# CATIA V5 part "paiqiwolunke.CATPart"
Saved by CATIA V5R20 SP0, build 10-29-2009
Part number: paiqiwolunke
Material "无"
Bounding box of the stored display mesh (mm): x -181.093 to 108.493, y -161.62 to 108.435, z -157.748 to -20.517
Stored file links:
  C:\Users\Administrator\Desktop\paiqiwolunke.CATPart
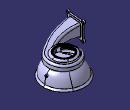
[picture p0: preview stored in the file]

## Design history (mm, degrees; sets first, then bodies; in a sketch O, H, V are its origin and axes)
Body1 (main body), material "无"
  DatumSurface1
  Sketch1 on face of DatumSurface1, origin (0, 0, -46.0268), H (1, 0, 0), V (0, 1, 0)
    circle A1 centre (0, 0) radius 48
    circle A2 centre (0, 0) radius 41
    radius A1 = 48
    radius A2 = 41
  Pad1: profile Sketch1, direction (0, 0, -1), length 4
  Fillet1: radius 1, on edge [face of Pad1 from Sketch1.A1 | start face of Pad1]
  Plane1: type Offset, RefPlane xy-plane, Offset -72
  Sketch2 on Plane1, origin (0, 0, -72), H (1, 0, 0), V (0, 1, 0)
    arc A1 centre (0, 0) radius 62.4525 from (38.718, -49.0024) to (-57.1138, -25.2652) ccw
    spline S1 through (38.718, -49.0024) (-43.2646, -95.0784) (-167.0197, -110.3887)
    point P2 (38.718, -49.0024)
    spline S2 through (-57.1138, -25.2652) (-47.5761, -37.3017) (-28.4968, -46.2262)
    point P3 (38.718, -49.0024)
    point P4 (-57.1138, -25.2652)
    coincidence: P3 A1, P3 P2, P4 A1
    tangency: S1 A1
  Set1
    Point1: type OnCurve, Support Sketch2, Length 107.0833 {= length(Sketch2) / 5}
    Point2: type OnCurve, Support Sketch2, Length 214.1665 {= (length(Sketch2)) * 2 / 5}
    Point3: type OnCurve, Support Sketch2, Length 321.2498 {= (length(Sketch2)) * 3 / 5}
    Point4: type OnCurve, Support Sketch2, Length 428.3331 {= (length(Sketch2)) * 4 / 5}
  Plane2: type Normal, Curve Sketch2, RefPoint vertex of Sketch2
  Plane3: type Normal, Curve Sketch2, RefPoint Point1
  Plane4: type Normal, Curve Sketch2, RefPoint Point2
  Plane5: type Normal, Curve Sketch2, RefPoint Point3
  Plane6: type Normal, Curve Sketch2, RefPoint Point4
  Plane7: type Normal, Curve Sketch2, RefPoint vertex of Sketch2
  Sketch3 on Plane2, origin (-156.975, 12.7997, 0), H (0.0813, 0.9967, 0), V (0, 0, 1)
    point P1 (-157.5972, -38)
    line L1 (-149.3665, -38) -> (-97.6756, -38)
    line L2 (-89.5972, -46.0784) -> (-89.5972, -98.0619)
    line L3 (-97.5353, -106) -> (-148.2395, -106)
    line L4 (-157.5972, -96.6423) -> (-157.5972, -46.2307)
    point P2 (-89.5972, -106)
    point P3 (-157.5972, -106)
    reference projected point E1 (-123.5972, -72) from vertex of Sketch2
    reference projected point E2 (-123.5972, -72) from vertex of Sketch2
    arc A1 centre (-149.3665, -46.2307) radius 8.2307 from (-157.5972, -46.2307) to (-149.3665, -38) cw
    arc A2 centre (-97.6756, -46.0784) radius 8.0784 from (-97.6756, -38) to (-89.5972, -46.0784) cw
    arc A3 centre (-97.5353, -98.0619) radius 7.9381 from (-89.5972, -98.0619) to (-97.5353, -106) cw
    arc A4 centre (-148.2395, -96.6423) radius 9.3577 from (-148.2395, -106) to (-157.5972, -96.6423) cw
    arc A5 centre (-97.5353, -98.0619) radius 5.5029 from (-97.5353, -103.5648) to (-92.0324, -98.0619) ccw
    line L5 (-92.0324, -98.0619) -> (-92.0324, -46.0784)
    arc A6 centre (-97.6756, -46.0784) radius 5.6432 from (-92.0324, -46.0784) to (-97.6756, -40.4352) ccw
    line L6 (-149.3665, -40.4352) -> (-97.6756, -40.4352)
    arc A7 centre (-149.3665, -46.2307) radius 5.7955 from (-149.3665, -40.4352) to (-155.162, -46.2307) ccw
    line L7 (-155.162, -46.2307) -> (-155.162, -96.6423)
    arc A8 centre (-148.2395, -96.6423) radius 6.9225 from (-155.162, -96.6423) to (-148.2395, -103.5648) ccw
    line L8 (-97.5353, -103.5648) -> (-148.2395, -103.5648)
    distance P3 P1 = 68
    radius A1 = 8.2307
    radius A2 = 8.0784
    distance P2 P3 = 68
    radius A3 = 7.9381
    radius A4 = 9.3577
    horizontal: L1 H, L3 H
    vertical: L2 V, L4 V
    equidistance: L4 L2 E1, L3 L1 E2
    coincidence: L4 P1, L1 P1, L2 P2, L3 P2, L3 P3, L4 P3
    tangency: A1 L4, A1 L1, A2 L1, A2 L2, A3 L2, A3 L3, A4 L3, A4 L4
  Sketch4 on Plane3, origin (-83.5491, -21.2744, 0), H (-0.2735, 0.9619, 0), V (0, 0, 1)
    point P1 (-106.6399, -48)
    line L1 (-97.0585, -48) -> (-68.4469, -48)
    line L2 (-58.6399, -57.8069) -> (-58.6399, -87.414)
    line L3 (-67.2259, -96) -> (-98.3631, -96)
    line L4 (-106.6399, -87.7232) -> (-106.6399, -57.5814)
    point P2 (-58.6399, -96)
    point P3 (-106.6399, -96)
    reference projected point E1 (-82.6399, -72) from Point1
    reference projected point E2 (-82.6399, -72) from Point1
    arc A1 centre (-98.3631, -87.7232) radius 8.2768 from (-106.6399, -87.7232) to (-98.3631, -96) ccw
    arc A2 centre (-67.2259, -87.414) radius 8.586 from (-67.2259, -96) to (-58.6399, -87.414) ccw
    arc A3 centre (-68.4469, -57.8069) radius 9.8069 from (-58.6399, -57.8069) to (-68.4469, -48) ccw
    arc A4 centre (-97.0585, -57.5814) radius 9.5814 from (-97.0585, -48) to (-106.6399, -57.5814) ccw
    arc A5 centre (-97.2584, -57.5576) radius 7.6536 from (-97.2584, -49.904) to (-104.912, -57.5576) ccw
    line L5 (-104.912, -57.5576) -> (-104.912, -87.6994)
    arc A6 centre (-98.563, -87.6994) radius 6.349 from (-104.912, -87.6994) to (-98.563, -94.0484) ccw
    line L6 (-67.4258, -94.0484) -> (-98.563, -94.0484)
    arc A7 centre (-67.4258, -87.3902) radius 6.6582 from (-67.4258, -94.0484) to (-60.7676, -87.3902) ccw
    line L7 (-60.7676, -87.3902) -> (-60.7676, -57.7831)
    arc A8 centre (-68.6467, -57.7831) radius 7.8792 from (-60.7676, -57.7831) to (-68.6467, -49.904) ccw
    line L8 (-97.2584, -49.904) -> (-68.6467, -49.904)
    distance P3 P1 = 48
    distance P2 P3 = 48
    radius A1 = 8.2768
    radius A2 = 8.586
    radius A3 = 9.8069
    radius A4 = 9.5814
    horizontal: L1 H, L3 H
    vertical: L2 V, L4 V
    equidistance: L3 L1 E1, L4 L2 E2
    coincidence: L4 P3, L3 P3, L3 P2, L2 P2, L1 P1, L4 P1
    tangency: A1 L4, A1 L3, A2 L3, A2 L2, A3 L2, A3 L1, A4 L1, A4 L4
  Sketch5 on Plane4, origin (-4.1333, -2.5181, 0), H (-0.6055, 0.7958, 0), V (0, 0, 1)
    point P1 (-82.9955, -52)
    line L1 (-73.3955, -52) -> (-52.5955, -52)
    line L2 (-42.9955, -61.6) -> (-42.9955, -82.4)
    line L3 (-52.5955, -92) -> (-73.3955, -92)
    line L4 (-82.9955, -82.4) -> (-82.9955, -61.6)
    point P2 (-42.9955, -92)
    point P3 (-82.9955, -92)
    reference projected point E1 (-62.9955, -72) from Point2
    reference projected point E2 (-62.9955, -72) from Point2
    arc A1 centre (-73.3955, -82.4) radius 9.6 from (-82.9955, -82.4) to (-73.3955, -92) ccw
    arc A2 centre (-52.5955, -82.4) radius 9.6 from (-52.5955, -92) to (-42.9955, -82.4) ccw
    arc A3 centre (-52.5955, -61.6) radius 9.6 from (-52.5955, -52) to (-42.9955, -61.6) cw
    arc A4 centre (-73.3955, -61.6) radius 9.6 from (-73.3955, -52) to (-82.9955, -61.6) ccw
    arc A5 centre (-49.6836, -82.554) radius 7.5157 from (-49.6836, -90.0697) to (-42.1679, -82.554) ccw
    line L5 (-42.1679, -82.554) -> (-42.1679, -61.754)
    arc A6 centre (-49.6836, -61.754) radius 7.5157 from (-42.1679, -61.754) to (-49.6836, -54.2383) ccw
    line L6 (-70.4836, -54.2383) -> (-49.6836, -54.2383)
    arc A7 centre (-70.4836, -61.754) radius 7.5157 from (-70.4836, -54.2383) to (-77.9992, -61.754) ccw
    line L7 (-77.9992, -61.754) -> (-77.9992, -82.554)
    arc A8 centre (-70.4836, -82.554) radius 7.5157 from (-77.9992, -82.554) to (-70.4836, -90.0697) ccw
    line L8 (-49.6836, -90.0697) -> (-70.4836, -90.0697)
    distance P3 P1 = 40
    distance P2 P3 = 40
    radius A1 = 9.6
    radius A2 = 9.6
    radius A3 = 9.6
    radius A4 = 9.6
    horizontal: L1 H, L3 H
    vertical: L2 V, L4 V
    equidistance: L4 L2 E1, L3 L1 E2
    coincidence: L4 P3, L3 P3, L3 P2, L2 P2, L1 P1, L4 P1
    tangency: A1 L4, A1 L3, A2 L3, A2 L2, A3 L1, A3 L2, A4 L1, A4 L4
  Sketch6 on Plane5, origin (0, 0, 0), H (-0.7537, -0.6572, 0), V (0, 0, 1)
    point P1 (-80.4525, -54)
    line L1 (-70.8525, -54) -> (-54.0525, -54)
    line L2 (-44.4525, -63.6) -> (-44.4525, -80.4)
    line L3 (-54.0525, -90) -> (-70.8525, -90)
    line L4 (-80.4525, -80.4) -> (-80.4525, -63.6)
    point P2 (-44.4525, -90)
    point P3 (-80.4525, -90)
    reference projected point E1 (-62.4525, -72) from Point3
    reference projected point E2 (-62.4525, -72) from Point3
    arc A1 centre (-70.8525, -63.6) radius 9.6 from (-70.8525, -54) to (-80.4525, -63.6) ccw
    arc A2 centre (-70.8525, -80.4) radius 9.6 from (-80.4525, -80.4) to (-70.8525, -90) ccw
    arc A3 centre (-54.0525, -80.4) radius 9.6 from (-54.0525, -90) to (-44.4525, -80.4) ccw
    arc A4 centre (-54.0525, -63.6) radius 9.6 from (-44.4525, -63.6) to (-54.0525, -54) ccw
    arc A5 centre (-50.5792, -80.4111) radius 7.8791 from (-50.5792, -88.2902) to (-42.7001, -80.4111) ccw
    line L5 (-42.7001, -80.4111) -> (-42.7001, -63.6111)
    arc A6 centre (-50.5792, -63.6111) radius 7.8791 from (-42.7001, -63.6111) to (-50.5792, -55.732) ccw
    line L6 (-67.3792, -55.732) -> (-50.5792, -55.732)
    arc A7 centre (-67.3792, -63.6111) radius 7.8791 from (-67.3792, -55.732) to (-75.2584, -63.6111) ccw
    line L7 (-75.2584, -63.6111) -> (-75.2584, -80.4111)
    arc A8 centre (-67.3792, -80.4111) radius 7.8791 from (-75.2584, -80.4111) to (-67.3792, -88.2902) ccw
    line L8 (-50.5792, -88.2902) -> (-67.3792, -88.2902)
    distance P3 P1 = 36
    radius A1 = 9.6
    distance P2 P3 = 36
    radius A2 = 9.6
    radius A3 = 9.6
    radius A4 = 9.6
    horizontal: L1 H, L3 H
    vertical: L2 V, L4 V
    equidistance: L2 L4 E1, L1 L3 E2
    coincidence: L1 P1, L4 P1, L4 P3, L3 P3, L3 P2, L2 P2
    tangency: A1 L1, A1 L4, A2 L4, A2 L3, A3 L3, A3 L2, A4 L2, A4 L1
  Sketch7 on Plane6, origin (0, 0, 0), H (0.7585, -0.6517, 0), V (0, 0, 1)
    line L1 (-65.699, -54.5) -> (-49.699, -54.5)
    line L2 (-40.199, -64) -> (-40.199, -80)
    line L3 (-49.699, -89.5) -> (-65.699, -89.5)
    line L4 (-75.199, -80) -> (-75.199, -64)
    reference projected point E1 (-62.4525, -72) from Point4
    arc A1 centre (-65.699, -80) radius 9.5 from (-75.199, -80) to (-65.699, -89.5) ccw
    arc A2 centre (-49.699, -80) radius 9.5 from (-40.199, -80) to (-49.699, -89.5) cw
    arc A3 centre (-49.699, -64) radius 9.5 from (-49.699, -54.5) to (-40.199, -64) cw
    arc A4 centre (-65.699, -64) radius 9.5 from (-65.699, -54.5) to (-75.199, -64) ccw
    line L5 (-46.6872, -88.3521) -> (-62.6872, -88.3521)
    arc A5 centre (-62.6872, -80.0426) radius 8.3095 from (-70.9967, -80.0426) to (-62.6872, -88.3521) ccw
    line L6 (-70.9967, -64.0426) -> (-70.9967, -80.0426)
    arc A6 centre (-62.6872, -64.0426) radius 8.3095 from (-62.6872, -55.7331) to (-70.9967, -64.0426) ccw
    line L7 (-62.6872, -55.7331) -> (-46.6872, -55.7331)
    arc A7 centre (-46.6872, -64.0426) radius 8.3095 from (-38.3777, -64.0426) to (-46.6872, -55.7331) ccw
    line L8 (-38.3777, -80.0426) -> (-38.3777, -64.0426)
    arc A8 centre (-46.6872, -80.0426) radius 8.3095 from (-46.6872, -88.3521) to (-38.3777, -80.0426) ccw
    distance L4 L2 = 35
    distance L3 L1 = 35
    radius A1 = 9.5
    radius A2 = 9.5
    radius A3 = 9.5
    radius A4 = 9.5
    horizontal: L1 H, L3 H
    vertical: L2 V, L4 V
    equidistance: L1 L3 E1
    tangency: A1 L4, A1 L3, A2 L2, A2 L3, A3 L1, A3 L2, A4 L1, A4 L4
  Sketch8 on Plane7, origin (-18.4459, 3.7125, 0), H (0.1973, 0.9803, 0), V (0, 0, 1)
    point P1 (-53.4662, -59)
    line L1 (-42.6821, -59) -> (-38.0662, -59)
    line L2 (-33.4662, -63.6) -> (-33.4662, -80.4)
    line L3 (-38.0662, -85) -> (-42.2918, -85)
    line L4 (-53.4662, -73.8257) -> (-53.4662, -69.7841)
    point P2 (-33.4662, -85)
    point P3 (-53.4662, -85)
    reference projected point E1 (-50.9401, -72) from vertex of Sketch2
    arc A1 centre (-42.6821, -69.7841) radius 10.7841 from (-42.6821, -59) to (-53.4662, -69.7841) ccw
    arc A2 centre (-42.2918, -73.8257) radius 11.1743 from (-53.4662, -73.8257) to (-42.2918, -85) ccw
    arc A3 centre (-38.0662, -80.4) radius 4.6 from (-38.0662, -85) to (-33.4662, -80.4) ccw
    arc A4 centre (-38.0662, -63.6) radius 4.6 from (-38.0662, -59) to (-33.4662, -63.6) cw
    line L5 (-31.7117, -80.7328) -> (-31.7117, -63.9328)
    arc A5 centre (-35.0688, -63.9328) radius 3.3571 from (-31.7117, -63.9328) to (-35.0688, -60.5757) ccw
    line L6 (-39.6847, -60.5757) -> (-35.0688, -60.5757)
    arc A6 centre (-39.6847, -70.1169) radius 9.5412 from (-39.6847, -60.5757) to (-49.2259, -70.1169) ccw
    line L7 (-49.2259, -70.1169) -> (-49.2259, -74.1584)
    arc A7 centre (-39.2945, -74.1584) radius 9.9315 from (-49.2259, -74.1584) to (-39.2945, -84.0899) ccw
    line L8 (-35.0688, -84.0899) -> (-39.2945, -84.0899)
    arc A8 centre (-35.0688, -80.7328) radius 3.3571 from (-35.0688, -84.0899) to (-31.7117, -80.7328) ccw
    distance P3 P1 = 26
    radius A1 = 10.7841
    distance P2 P3 = 20
    radius A2 = 11.1743
    radius A3 = 4.6
    radius A4 = 4.6
    horizontal: L1 H, L3 H
    vertical: L2 V, L4 V
    equidistance: L3 L1 E1
    coincidence: L1 P1, L4 P1, L4 P3, L3 P3, L3 P2, L2 P2
    tangency: A1 L1, A1 L4, A2 L4, A2 L3, A3 L3, A3 L2, A4 L1, A4 L2
  MultiExtract1: ListOfMultiExtractConstraints (MultiExtractConstraint Sketch3.L4; MultiExtractConstraint Sketch3.A4; MultiExtractConstraint Sketch3.L3; MultiExtractConstraint Sketch3.A3; MultiExtractConstraint Sketch3.L2; MultiExtractConstraint Sketch3.A2; MultiExtractConstraint Sketch3.L1; MultiExtractConstraint Sketch3.A1)
  MultiExtract2: ListOfMultiExtractConstraints (MultiExtractConstraint Sketch4.A1; MultiExtractConstraint Sketch4.L3; MultiExtractConstraint Sketch4.A2; MultiExtractConstraint Sketch4.L2; MultiExtractConstraint Sketch4.A3; MultiExtractConstraint Sketch4.L1; MultiExtractConstraint Sketch4.A4; MultiExtractConstraint Sketch4.L4)
  MultiExtract3: ListOfMultiExtractConstraints (MultiExtractConstraint Sketch5.L4; MultiExtractConstraint Sketch5.A1; MultiExtractConstraint Sketch5.L3; MultiExtractConstraint Sketch5.A2; MultiExtractConstraint Sketch5.L2; MultiExtractConstraint Sketch5.A3; MultiExtractConstraint Sketch5.L1; MultiExtractConstraint Sketch5.A4)
  MultiExtract4: ListOfMultiExtractConstraints (MultiExtractConstraint Sketch6.A3; MultiExtractConstraint Sketch6.L3; MultiExtractConstraint Sketch6.A2; MultiExtractConstraint Sketch6.L4; MultiExtractConstraint Sketch6.A1; MultiExtractConstraint Sketch6.L1; MultiExtractConstraint Sketch6.A4; MultiExtractConstraint Sketch6.L2)
  MultiExtract5: ListOfMultiExtractConstraints (MultiExtractConstraint Sketch7.L4; MultiExtractConstraint Sketch7.A1; MultiExtractConstraint Sketch7.L3; MultiExtractConstraint Sketch7.A2; MultiExtractConstraint Sketch7.L2; MultiExtractConstraint Sketch7.A3; MultiExtractConstraint Sketch7.L1; MultiExtractConstraint Sketch7.A4)
  MultiExtract6: ListOfMultiExtractConstraints (MultiExtractConstraint Sketch8.A1; MultiExtractConstraint Sketch8.L1; MultiExtractConstraint Sketch8.A4; MultiExtractConstraint Sketch8.L2; MultiExtractConstraint Sketch8.A3; MultiExtractConstraint Sketch8.L3; MultiExtractConstraint Sketch8.A2; MultiExtractConstraint Sketch8.L4)
  Loft1: solid, Sections (MultiExtract1; MultiExtract2; MultiExtract3; MultiExtract4; MultiExtract5; MultiExtract6)
  MultiExtract7: ListOfMultiExtractConstraints (MultiExtractConstraint Sketch3.L6; MultiExtractConstraint Sketch3.A6; MultiExtractConstraint Sketch3.L5; MultiExtractConstraint Sketch3.A5; MultiExtractConstraint Sketch3.L8; MultiExtractConstraint Sketch3.A8; MultiExtractConstraint Sketch3.L7; MultiExtractConstraint Sketch3.A7)
  MultiExtract8: ListOfMultiExtractConstraints (MultiExtractConstraint Sketch4.A5; MultiExtractConstraint Sketch4.L5; MultiExtractConstraint Sketch4.A6; MultiExtractConstraint Sketch4.L6; MultiExtractConstraint Sketch4.A7; MultiExtractConstraint Sketch4.L7; MultiExtractConstraint Sketch4.A8; MultiExtractConstraint Sketch4.L8)
  MultiExtract9: ListOfMultiExtractConstraints (MultiExtractConstraint Sketch5.L7; MultiExtractConstraint Sketch5.A8; MultiExtractConstraint Sketch5.L8; MultiExtractConstraint Sketch5.A7; MultiExtractConstraint Sketch5.L6; MultiExtractConstraint Sketch5.A6; MultiExtractConstraint Sketch5.L5; MultiExtractConstraint Sketch5.A5)
  MultiExtract10: ListOfMultiExtractConstraints (MultiExtractConstraint Sketch6.L8; MultiExtractConstraint Sketch6.A8; MultiExtractConstraint Sketch6.L7; MultiExtractConstraint Sketch6.A7; MultiExtractConstraint Sketch6.L6; MultiExtractConstraint Sketch6.A6; MultiExtractConstraint Sketch6.L5; MultiExtractConstraint Sketch6.A5)
  MultiExtract11: ListOfMultiExtractConstraints (MultiExtractConstraint Sketch7.L7; MultiExtractConstraint Sketch7.A6; MultiExtractConstraint Sketch7.L6; MultiExtractConstraint Sketch7.A5; MultiExtractConstraint Sketch7.L5; MultiExtractConstraint Sketch7.A8; MultiExtractConstraint Sketch7.L8; MultiExtractConstraint Sketch7.A7)
  MultiExtract12: ListOfMultiExtractConstraints (MultiExtractConstraint Sketch8.L5; MultiExtractConstraint Sketch8.A8; MultiExtractConstraint Sketch8.A7; MultiExtractConstraint Sketch8.L8; MultiExtractConstraint Sketch8.A6; MultiExtractConstraint Sketch8.L6; MultiExtractConstraint Sketch8.A5; MultiExtractConstraint Sketch8.L7)
  Loft2: solid, Sections (MultiExtract7; MultiExtract8; MultiExtract9; MultiExtract10; MultiExtract11; MultiExtract12)
  Plane8: type Offset, RefPlane Plane1, Offset -15
  Plane9: type Offset, RefPlane Plane1, Offset 12
  Sketch9 on Plane9, origin (0, 0, -60), H (1, 0, 0), V (0, 1, 0)
    circle A1 centre (1.3796, -4.5256) radius 61.7151
  Loft3: Sections (edge [face of Pad1 from Sketch1.A2 | end face of Pad1]; Sketch9)
  ThickSurface1: Surface Loft3, TopOffset 5, BotOffset 0
  Sketch10 on Plane8, origin (0, 0, -87), H (1, 0, 0), V (0, 1, 0)
    circle A1 centre (2.4934, -2.0884) radius 61.7432
  Plane10: type Offset, RefPlane Plane8, Offset -32
  Plane11: type Offset, RefPlane Plane10, Offset -28
  Sketch11 on Plane10, origin (0, 0, -119), H (1, 0, 0), V (0, 1, 0)
    circle A1 centre (2.4934, -2.0884) radius 89.8824
    reference projected circle E1 centre (2.4934, -2.0884) radius 61.7432 from Sketch10.A1
    concentricity: A1 E1
  Sketch12 on Plane11, origin (0, 0, -147), H (1, 0, 0), V (0, 1, 0)
    circle A1 centre (0, 0) radius 98.0083
  Loft4: Sections (Sketch10; Sketch11; Sketch12)
  ThickSurface2: Surface Loft4, TopOffset 2, BotOffset 3
  Plane12: type Offset, RefPlane Plane8, Offset -12
  Sketch13 on Plane12, origin (0, 0, -99), H (1, 0, 0), V (0, 1, 0)
    circle A1 centre (0, 0) radius 20.54
    circle A2 centre (-0.0225, 0.0191) radius 68.5173
    reference projected curve E1 from edge [face of ThickSurface2 | face of ThickSurface2]
    concentricity: A2 E1
  Pad2: profile Sketch13, direction (0, 0, 1), length 3
  Fillet2: radius 1, on edge [face of Pad2 from Sketch13.A1 | start face of Pad2]; edge [end face of Pad2 | face of Pad2 from Sketch13.A1]
  Sketch14 on Plane1, origin (0, 0, -72), H (1, 0, 0), V (0, 1, 0)
    arc A1 centre (0, 0) radius 69.3759 from (-69.0256, 6.9637) to (-19.0511, -66.7089) ccw
  Plane13: type Normal, Curve Sketch14
  Sketch15 on Plane13, origin (0, 0, 0), H (0.8276, 0.5614, 0), V (0, 0, 1)
    spline S1 through (-59.6577, -53.5603) (-70.3652, -71.7344) (-59.2766, -87.9066)
  Sweep1: type Unspec, Profile Sketch15, Guide Sketch14, AngleRef 0
  ThickSurface3: Surface Sweep1, TopOffset 2, BotOffset 1
  Sketch16 on face of Loft1, origin (-156.975, 12.7997, 0), H (0.0813, 0.9967, 0), V (0, 0, 1)
    projected line E1 (-92.0324, -98.0619) -> (-92.0324, -46.0784) from edge [face of Loft2 | face of Loft1]
    projected arc E2 centre (-97.6756, -46.0784) radius 5.6432 from (-92.0324, -46.0784) to (-97.6756, -40.4352) ccw from edge [face of Loft2 | face of Loft1]
    projected line E3 (-97.6756, -40.4352) -> (-149.3665, -40.4352) from edge [face of Loft2 | face of Loft1]
    projected arc E4 centre (-149.3666, -46.2307) radius 5.7955 from (-149.3665, -40.4352) to (-155.162, -46.2307) ccw from edge [face of Loft2 | face of Loft1]
    projected line E5 (-155.162, -46.2307) -> (-155.162, -96.6423) from edge [face of Loft2 | face of Loft1]
    projected arc E6 centre (-148.2396, -96.6424) radius 6.9225 from (-155.162, -96.6423) to (-148.2395, -103.5648) ccw from edge [face of Loft2 | face of Loft1]
    projected line E7 (-148.2395, -103.5648) -> (-97.5353, -103.5648) from edge [face of Loft2 | face of Loft1]
    projected arc E8 centre (-97.5353, -98.0619) radius 5.5029 from (-97.5353, -103.5648) to (-92.0324, -98.0619) ccw from edge [face of Loft2 | face of Loft1]
    point P17 (-81.1295, -101.0273)
    point P18 (-81.1295, -103.5648)
    line L1 (-80.0324, -36.4352) -> (-80.0324, -107.5648)
    line L2 (-88.0324, -115.5648) -> (-159.162, -115.5648)
    circle A1 centre (-167.162, -28.4352) radius 5
    circle A2 centre (-80.0324, -28.4352) radius 5
    circle A3 centre (-80.0324, -115.5648) radius 5
    arc A4 centre (-167.162, -28.4352) radius 8 from (-159.162, -28.4352) to (-167.162, -36.4352) ccw
    arc A5 centre (-80.0324, -28.4352) radius 8 from (-80.0324, -36.4352) to (-88.0324, -28.4352) ccw
    arc A6 centre (-167.162, -115.5648) radius 8 from (-167.162, -107.5648) to (-159.162, -115.5648) ccw
    arc A7 centre (-80.0324, -115.5648) radius 8 from (-88.0324, -115.5648) to (-80.0324, -107.5648) ccw
    line L3 (-159.162, -28.4352) -> (-88.0324, -28.4352)
    line L4 (-167.162, -107.5648) -> (-167.162, -36.4352)
    circle A8 centre (-167.162, -115.5648) radius 5
    point P31 (-167.162, -112.2727)
    distance L1 E1 = 12
    distance E7 L2 = 12
    radius A3 = 5
    radius A1 = 5
    radius A2 = 5
    radius A4 = 8
    radius A6 = 8
    radius A7 = 8
    radius A5 = 8
    radius A8 = 5
    horizontal: L2 H, L3 H
    vertical: L1 V, L4 V
  Pad3: profile Sketch16, direction (-0.9967, 0.0813, 0), length 10
  Fillet3: radius 1, on end face of Pad3
  Fillet4: radius 1, on start face of Pad3
  Fillet5: radius 1, on edge [start face of Pad2 | face of Pad2 from Sketch13.A2]
  Plane14: type Offset, RefPlane Plane8, Offset -70
  Sketch17 on Plane14, origin (0, 0, -157), H (1, 0, 0), V (0, 1, 0)
    circle A1 centre (0, 0) radius 106.4305
  Loft5: Sections (edge [face of ThickSurface2 | face of ThickSurface2]; Sketch17)
  ThickSurface4: Surface Loft5, TopOffset 3, BotOffset 1
  Fillet6: radius 1, on edge [face of ThickSurface2 | face of ThickSurface2]
  Sketch18 on start face of Pad2, origin (0, 0, -99), H (1, 0, 0), V (0, 1, 0)
    circle A1 centre (47.4681, 0) radius 14.0099
    point P1 (47.4681, 0)
    coincidence: P1 H
  Pocket1: profile Sketch18, direction (0, 0, 1), length 4
  Sketch19 on yz-plane, origin (0, 0, 0), H (0, 1, 0), V (0, 0, 1)
    circle A1 centre (0, -110.347) radius 4.4967
    point P1 (0, -110.347)
    coincidence: P1 V
  Pocket2: profile Sketch19, direction (1, 0, 0), through (limit type 3)
  Plane15: type Offset, RefPlane yz-plane, Offset 88
  DatumCurve1
  Sketch20 on Plane15, origin (88, 0, 0), H (0, 1, 0), V (0, 0, 1)
    projected circle E1 centre (0, -110.5687) radius 3.113 from edge of DatumCurve1
    circle A1 centre (0, -110.5687) radius 6.2949
    point P1 (0, -110.5687)
    concentricity: P1 E1
  Pad4: profile Sketch20, direction (1, 0, 0), length 8
  Fillet7: radius 0.3, on edge [face of Pad4 from Sketch20.A1 | end face of Pad4]; edge [face of Pad4 from Sketch20.A1 | face of ThickSurface2]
